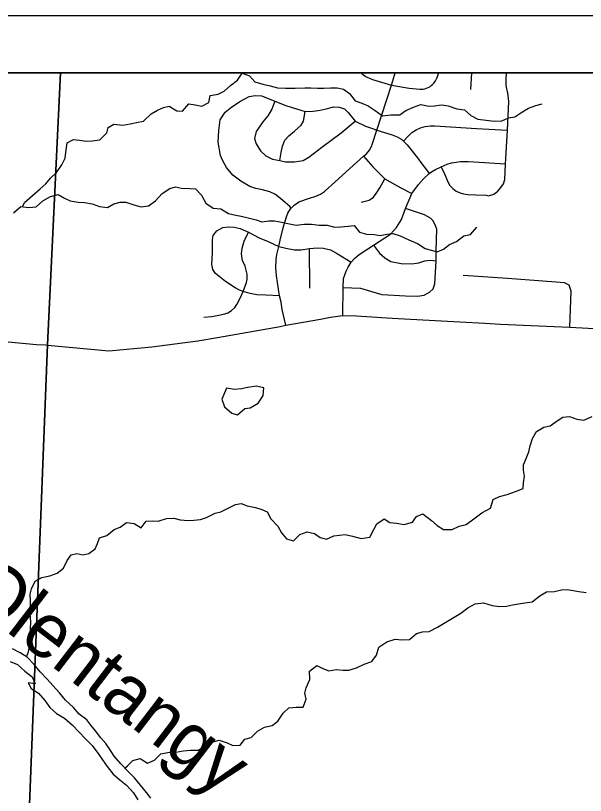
# Model space of a CAD drawing. Extents: x 0 to 34, y 0 to 22.
# Drawn here: x 17.909 to 18.903, y 8.924 to 10.284 of the extents above; entities that cross this region are included whole.
import ezdxf

# ---------------------------------------------------------------- set-up
doc = ezdxf.new("R2010")
doc.units = 0
for name, color, linetype in [('GM_X_Corporation', 7, 'Continuous'), ('GM_X_Major_River', 7, 'Continuous'), ('GM_X_Major_River_Text', 7, 'Continuous'), ('GM_X_Minor_Lake', 7, 'Continuous'), ('GM_X_Minor_River', 7, 'Continuous'), ('GM_X_State_Route', 7, 'Continuous'), ('GM_X_Township_Road', 7, 'Continuous'), ('SH_Data', 7, 'Continuous')]:
    doc.layers.add(name, color=color, linetype=linetype)

msp = doc.modelspace()

# ---------------------------------------------------------------- linework, layer by layer
at = {"layer": 'GM_X_Corporation'}
for points in [[(15.3473, 8.5302), (16.0546, 8.4904), (16.2652, 8.4813), (16.5003, 8.4668), (16.6112, 8.4601), (16.8906, 8.4459), (17.9061, 8.3935), (17.9129, 8.3931), (18.0835, 8.3895), (18.0903, 8.3893), (19.1791, 8.3374), (19.2255, 8.335), (19.3372, 8.3286), (19.3853, 8.3266), (19.4457, 8.3236), (19.4724, 8.3227), (19.4766, 8.3225), (19.5203, 8.3202), (19.5346, 8.3197), (19.5646, 8.318), (19.5646, 10.1841), (12.7646, 10.1841)], [(15.3473, 8.5302), (16.0546, 8.4904), (16.2652, 8.4813), (16.5003, 8.4668), (16.6112, 8.4601), (16.8906, 8.4459), (17.9061, 8.3935), (17.9129, 8.3931), (17.9187, 8.5404), (17.9296, 8.8181), (17.9647, 9.7099), (17.9872, 10.1841), (13.2832, 10.1841)]]:
    msp.add_lwpolyline(points, dxfattribs=at)
msp.add_lwpolyline([(19.5646, 8.318), (19.5646, 10.1841), (17.9872, 10.1841), (17.9647, 9.7099), (17.9296, 8.8181), (17.9187, 8.5404), (17.9129, 8.3931), (18.0835, 8.3895), (18.0903, 8.3893), (19.1791, 8.3374), (19.2255, 8.335), (19.3372, 8.3286), (19.3853, 8.3266), (19.4457, 8.3236), (19.4724, 8.3227), (19.4766, 8.3225), (19.5203, 8.3202), (19.5346, 8.3197)], close=True, dxfattribs=at)
at = {"layer": 'GM_X_Major_River'}
for points in [[(18.0663, 9.0144), (18.058, 9.0239), (18.0486, 9.0361), (18.0404, 9.0461), (18.0332, 9.0556), (18.02, 9.0652), (18.0099, 9.077), (17.9963, 9.09), (17.9854, 9.1026), (17.9738, 9.1152), (17.964, 9.1263), (17.952, 9.1389), (17.9415, 9.1522), (17.929, 9.1648), (17.917, 9.1721), (17.9038, 9.1794)], [(17.8995, 9.1571), (17.9127, 9.152), (17.9255, 9.1406), (17.9379, 9.1302), (17.9435, 9.1181), (17.931, 9.12), (17.9363, 9.1098), (17.9491, 9.1017), (17.96, 9.0891), (17.9686, 9.0769), (17.9807, 9.0666), (17.9943, 9.0585), (18.0082, 9.0459), (18.0195, 9.0344), (18.0308, 9.0222), (18.0428, 9.0104), (18.0541, 8.9951), (18.0604, 8.9856), (18.0687, 8.9738), (18.0792, 8.9608), (18.0909, 8.9505), (18.1026, 8.9413), (18.115, 8.9283), (18.1221, 8.9157)], [(18.1452, 8.919), (18.1373, 8.9285), (18.1268, 8.9415), (18.1163, 8.9541), (18.105, 8.9656), (18.0929, 8.9785), (18.0809, 8.9923), (18.0727, 9.0049), (18.0663, 9.0144)]]:
    msp.add_lwpolyline(points, dxfattribs=at)
at = {"layer": 'GM_X_Minor_Lake'}
for points in [[(18.2769, 9.634), (18.2689, 9.6147), (18.2735, 9.6018), (18.286, 9.5904), (18.2962, 9.5877), (18.3087, 9.5984), (18.3185, 9.5999), (18.3321, 9.6082), (18.3366, 9.615)], [(18.3366, 9.615), (18.3408, 9.6215), (18.342, 9.6344), (18.3287, 9.6378), (18.3143, 9.6352), (18.303, 9.6329), (18.2909, 9.6318), (18.2769, 9.634)]]:
    msp.add_lwpolyline(points, dxfattribs=at)
at = {"layer": 'GM_X_Minor_River'}
for points in [[(17.9209, 9.9507), (17.9244, 9.9578), (17.9383, 9.9704), (17.952, 9.9821), (17.9618, 9.9905), (17.9701, 10.0007), (17.9803, 10.0106), (17.9898, 10.0235), (17.9955, 10.0356), (17.9974, 10.05), (17.9989, 10.0622), (18.0102, 10.0682), (18.0204, 10.0667), (18.0329, 10.0648), (18.0428, 10.0659), (18.056, 10.0675), (18.0681, 10.0796), (18.0704, 10.0891), (18.0806, 10.0944), (18.0961, 10.0932), (18.109, 10.0951), (18.12, 10.0974), (18.1324, 10.1001), (18.1453, 10.1126), (18.1567, 10.119), (18.1672, 10.1239), (18.1771, 10.1262), (18.1903, 10.1182), (18.2002, 10.1175), (18.2115, 10.13), (18.2221, 10.1285), (18.2342, 10.1262), (18.246, 10.1327), (18.2482, 10.1448), (18.2626, 10.1471), (18.2728, 10.152), (18.2838, 10.1619), (18.2959, 10.1713), (18.3042, 10.1835), (18.3171, 10.1793), (18.3262, 10.1683), (18.3402, 10.1645), (18.3531, 10.1614), (18.3659, 10.158), (18.3799, 10.1573), (18.3966, 10.1573), (18.4136, 10.158), (18.4242, 10.158), (18.4356, 10.1576), (18.4465, 10.1576), (18.4583, 10.158), (18.47, 10.158), (18.481, 10.1557), (18.4912, 10.1481), (18.5014, 10.1356), (18.5132, 10.1314), (18.5238, 10.1269), (18.5363, 10.1185), (18.5491, 10.109), (18.5635, 10.1109), (18.579, 10.1109), (18.5896, 10.1185), (18.6029, 10.1246), (18.6161, 10.1291), (18.6297, 10.1261), (18.6399, 10.1268), (18.6521, 10.1287), (18.6634, 10.1268), (18.6789, 10.1215), (18.6922, 10.1196), (18.7032, 10.1097), (18.7153, 10.1037), (18.73, 10.1018), (18.744, 10.1002), (18.7569, 10.1006), (18.7686, 10.1059), (18.78, 10.1074), (18.7902, 10.1146), (18.8038, 10.1226), (18.8163, 10.1271), (18.8277, 10.1302)], [(17.9054, 9.94), (17.9183, 9.951), (17.9323, 9.9491), (17.9448, 9.9506), (17.9569, 9.9612), (17.9698, 9.9684), (17.9834, 9.9719), (17.9944, 9.9658), (18.0042, 9.9608), (18.0182, 9.9586), (18.0292, 9.9582), (18.0428, 9.9555), (18.0557, 9.9513), (18.0693, 9.9494), (18.0807, 9.9555), (18.0913, 9.9585), (18.1011, 9.9585), (18.1155, 9.954), (18.128, 9.9506), (18.1408, 9.9521), (18.1529, 9.9608), (18.1647, 9.9737), (18.1783, 9.9824), (18.1881, 9.9854), (18.1983, 9.9828), (18.2127, 9.9824), (18.2229, 9.9816), (18.2332, 9.9706), (18.2407, 9.957), (18.2536, 9.9482), (18.2669, 9.9467), (18.2805, 9.9391), (18.293, 9.9357), (18.3028, 9.9342), (18.3149, 9.9315), (18.3286, 9.9277), (18.3384, 9.9243), (18.3509, 9.9262), (18.3607, 9.9258), (18.3732, 9.9239), (18.3838, 9.9216), (18.3982, 9.9186), (18.4122, 9.9201), (18.4251, 9.9201), (18.4387, 9.9182), (18.4527, 9.9186), (18.4656, 9.9152), (18.4762, 9.9155), (18.4894, 9.9167), (18.4993, 9.9178), (18.5087, 9.906), (18.5212, 9.9026), (18.5345, 9.9022), (18.5451, 9.9007), (18.5564, 9.9026), (18.567, 9.9037), (18.5799, 9.8996), (18.595, 9.8927), (18.6102, 9.8863), (18.6234, 9.8779), (18.634, 9.8749), (18.6442, 9.8722), (18.6556, 9.8768), (18.6658, 9.8847), (18.6779, 9.89), (18.6908, 9.8999), (18.7025, 9.9022), (18.7135, 9.9147)], [(17.9281, 9.1654), (17.9319, 9.1743), (17.9338, 9.1872), (17.9346, 9.1986), (17.9349, 9.2134), (17.9357, 9.2263), (17.9345, 9.2395), (17.9349, 9.2521), (17.9349, 9.2623), (17.9345, 9.2744), (17.9368, 9.2839), (17.9432, 9.2976), (17.955, 9.304), (17.969, 9.3067), (17.9814, 9.3112), (17.9928, 9.3203), (17.9992, 9.3332), (18.006, 9.3435), (18.0159, 9.3454), (18.0261, 9.3431), (18.0371, 9.3454), (18.0477, 9.3537), (18.0518, 9.3632), (18.0552, 9.3727), (18.0685, 9.3769), (18.0809, 9.3875), (18.0912, 9.3913), (18.1025, 9.3996), (18.1158, 9.3981), (18.1282, 9.3905), (18.1369, 9.4019), (18.1472, 9.4026), (18.1578, 9.4019), (18.1721, 9.4064), (18.185, 9.4072), (18.196, 9.4045), (18.21, 9.403), (18.2202, 9.4037), (18.2316, 9.4049), (18.2422, 9.4087), (18.2573, 9.4162), (18.2671, 9.4185), (18.2796, 9.4246), (18.2929, 9.431), (18.3027, 9.4329), (18.3129, 9.4287), (18.3273, 9.4257), (18.3383, 9.4223), (18.3481, 9.4181), (18.3542, 9.406), (18.3663, 9.3934), (18.3731, 9.3817), (18.3815, 9.3714), (18.3936, 9.3676), (18.4049, 9.3786), (18.4174, 9.3832), (18.4303, 9.3805), (18.4405, 9.3737), (18.4511, 9.3706), (18.464, 9.3763), (18.4738, 9.3775), (18.484, 9.3786), (18.4965, 9.3756), (18.512, 9.3718), (18.5268, 9.3744), (18.5336, 9.3877), (18.5389, 9.3976), (18.5517, 9.4059), (18.5616, 9.3998), (18.5733, 9.3983), (18.5869, 9.396), (18.6013, 9.4002), (18.6085, 9.4104), (18.6195, 9.4146), (18.6346, 9.4032), (18.6445, 9.3945), (18.6555, 9.3873), (18.6706, 9.3876), (18.6827, 9.3933), (18.6948, 9.396), (18.7081, 9.4062), (18.7224, 9.4165), (18.7372, 9.4248), (18.7421, 9.44), (18.7531, 9.4449), (18.7663, 9.4483), (18.7811, 9.454), (18.7943, 9.4593), (18.7947, 9.4692), (18.7966, 9.4806), (18.7947, 9.4908), (18.7947, 9.5003), (18.7996, 9.5113), (18.8041, 9.5231), (18.8068, 9.5337), (18.8109, 9.5462), (18.8174, 9.5587), (18.8306, 9.5659), (18.8412, 9.5686), (18.8537, 9.5773), (18.8635, 9.5834)], [(18.8635, 9.5834), (18.8749, 9.5845), (18.8881, 9.58), (18.8999, 9.5784), (18.9146, 9.5849)], [(18.0997, 8.9712), (18.1042, 8.975), (18.1133, 8.9845), (18.1266, 8.9879), (18.1394, 8.9799), (18.1512, 8.9852), (18.1625, 8.9962), (18.1773, 8.9989), (18.1886, 8.9992), (18.2015, 9.0011), (18.2144, 9.0027), (18.228, 9.0023), (18.2408, 9.0114), (18.2511, 9.0167), (18.2643, 9.0197), (18.2779, 9.0152), (18.2878, 9.0106), (18.301, 9.0114), (18.309, 9.0216), (18.3199, 9.0246), (18.3309, 9.0356), (18.343, 9.0428), (18.3563, 9.0455), (18.3665, 9.0531), (18.3755, 9.0671), (18.3854, 9.0762), (18.3982, 9.0777), (18.4107, 9.0777), (18.416, 9.0914), (18.4138, 9.102), (18.4156, 9.1115), (18.4221, 9.1255), (18.4217, 9.1403), (18.4345, 9.1502), (18.4451, 9.1449), (18.4554, 9.1411), (18.4682, 9.143), (18.4803, 9.1422), (18.4902, 9.1422), (18.5038, 9.146), (18.5171, 9.1524), (18.5303, 9.157), (18.5386, 9.168), (18.5424, 9.1824), (18.5564, 9.1915), (18.5712, 9.1961), (18.5825, 9.1949), (18.5961, 9.1953), (18.6082, 9.2059), (18.6185, 9.2089), (18.6306, 9.2097), (18.6449, 9.2173), (18.6593, 9.226), (18.6741, 9.2343), (18.6854, 9.2415), (18.6979, 9.251), (18.7108, 9.2579), (18.7252, 9.2597), (18.7403, 9.2548), (18.7532, 9.2529), (18.7653, 9.254), (18.7759, 9.2563), (18.7861, 9.2578), (18.7971, 9.2593), (18.8103, 9.2612), (18.8236, 9.2719), (18.8353, 9.2787), (18.8489, 9.2794), (18.861, 9.2821), (18.8709, 9.2828), (18.8818, 9.2813), (18.8917, 9.2794), (18.9042, 9.2775)]]:
    msp.add_lwpolyline(points, dxfattribs=at)
at = {"layer": 'GM_X_State_Route'}
for points in [[(17.6666, 9.7372), (17.7408, 9.7296), (17.9454, 9.7105), (17.9612, 9.7097), (17.9649, 9.7093), (18.0719, 9.6992), (18.1468, 9.7063), (18.2271, 9.7165), (18.2615, 9.7226), (18.3705, 9.7416), (18.3806, 9.744), (18.4407, 9.7546), (18.4581, 9.7577), (18.4796, 9.7606), (18.5035, 9.7601), (18.5661, 9.7565), (18.684, 9.7499), (18.7272, 9.7474)], [(18.7272, 9.7474), (18.7546, 9.7458), (18.8482, 9.7416), (18.8759, 9.7408)], [(18.8759, 9.7408), (18.9398, 9.737), (18.9492, 9.7362), (19.0653, 9.7309), (19.0969, 9.7281), (19.1088, 9.7275)]]:
    msp.add_lwpolyline(points, dxfattribs=at)
at = {"layer": 'GM_X_Township_Road'}
for p, q in [((18.7032, 10.155), (18.705, 10.1841)), ((18.422, 9.8088), (18.4217, 9.8778))]:
    msp.add_line(p, q, dxfattribs=at)
for points in [[(18.3806, 9.744), (18.3741, 9.7716), (18.3721, 9.7844), (18.3696, 9.7954), (18.3641, 9.8298), (18.3632, 9.8441), (18.3638, 9.8585), (18.365, 9.8675), (18.368, 9.8812), (18.3705, 9.8923), (18.3766, 9.9163), (18.3813, 9.9329), (18.3837, 9.9394), (18.3886, 9.9468), (18.39, 9.9482), (18.3947, 9.9532), (18.4006, 9.9577), (18.4029, 9.9592), (18.4216, 9.9657), (18.4328, 9.9692), (18.4406, 9.9727), (18.4477, 9.9775), (18.4489, 9.9785), (18.4658, 9.9933), (18.4854, 10.0113), (18.516, 10.0386), (18.5209, 10.043), (18.5262, 10.0496), (18.5302, 10.057), (18.5312, 10.0594), (18.5391, 10.0842), (18.5645, 10.1629), (18.57, 10.1799), (18.5713, 10.1841)], [(18.5122, 10.1841), (18.5131, 10.1829), (18.5156, 10.1805), (18.518, 10.1788), (18.5183, 10.1783), (18.5318, 10.1726), (18.5645, 10.1629)], [(18.5645, 10.1629), (18.5956, 10.1577), (18.614, 10.1555), (18.6171, 10.1555), (18.6201, 10.1558), (18.6231, 10.1565), (18.626, 10.1574), (18.6288, 10.1586), (18.6315, 10.1601), (18.634, 10.1619), (18.6363, 10.1639), (18.6384, 10.1661), (18.6415, 10.1702), (18.6446, 10.1763), (18.6457, 10.1795), (18.6465, 10.1829), (18.6467, 10.1841)], [(18.764, 10.0349), (18.7668, 10.0844), (18.7695, 10.1342), (18.7674, 10.1491), (18.7668, 10.151), (18.765, 10.1593), (18.7645, 10.1636), (18.7645, 10.1721), (18.765, 10.1841)], [(18.39, 9.9482), (18.3871, 9.9512), (18.3795, 9.9579), (18.3718, 9.9642), (18.3651, 9.9699), (18.3612, 9.9723), (18.3526, 9.9765), (18.3396, 9.9803), (18.3279, 9.9822), (18.3177, 9.9857), (18.3017, 9.9951), (18.2881, 10.0056), (18.2767, 10.0189), (18.2697, 10.0318), (18.2664, 10.04), (18.2625, 10.0632), (18.2633, 10.0834), (18.266, 10.102), (18.2745, 10.1155), (18.2865, 10.1252), (18.3016, 10.1349), (18.3167, 10.1427), (18.3272, 10.1446), (18.338, 10.1442), (18.3516, 10.1388), (18.3613, 10.1349), (18.3802, 10.1275), (18.3988, 10.1213), (18.4143, 10.1167), (18.4279, 10.1175), (18.4402, 10.119), (18.4507, 10.1217), (18.4639, 10.1248), (18.4735, 10.1244), (18.4828, 10.1217), (18.489, 10.1151), (18.5014, 10.1), (18.5193, 10.0911), (18.5315, 10.087), (18.5391, 10.0842), (18.5657, 10.0759), (18.5744, 10.0727), (18.5825, 10.0677), (18.5858, 10.0649), (18.5922, 10.0589), (18.6098, 10.0362), (18.6177, 10.0255), (18.6257, 10.015), (18.6302, 10.0084)], [(18.3613, 10.1349), (18.3558, 10.1206), (18.3493, 10.1093), (18.3404, 10.0985), (18.3326, 10.0876), (18.3284, 10.0818), (18.326, 10.0698), (18.3284, 10.0601), (18.3361, 10.0481), (18.3458, 10.0392), (18.3574, 10.0338), (18.3702, 10.0315), (18.3798, 10.0288), (18.3953, 10.0288), (18.4108, 10.0311), (18.4205, 10.0373), (18.443, 10.0547), (18.4767, 10.0798), (18.5014, 10.1)], [(18.3702, 10.0315), (18.3725, 10.0454), (18.3744, 10.0563), (18.3787, 10.0667), (18.3857, 10.0741), (18.3953, 10.0822), (18.407, 10.0931), (18.4112, 10.1), (18.4143, 10.1167)], [(18.5858, 10.0649), (18.5939, 10.0739), (18.6004, 10.0802), (18.6076, 10.085), (18.6154, 10.0884), (18.6234, 10.0904), (18.6327, 10.0917), (18.6405, 10.0916), (18.6676, 10.0902), (18.7128, 10.0874), (18.7668, 10.0844)], [(18.4796, 9.7606), (18.4806, 9.8096), (18.4808, 9.8256), (18.4857, 9.8385), (18.4889, 9.8452), (18.4941, 9.854), (18.5004, 9.8606), (18.5085, 9.8673), (18.5218, 9.8758), (18.5333, 9.8834), (18.5631, 9.9026), (18.5732, 9.9145), (18.582, 9.9285), (18.5893, 9.9478), (18.6002, 9.9737), (18.6119, 9.9897), (18.6205, 9.9996), (18.6302, 10.0084), (18.6346, 10.0115), (18.6414, 10.0157), (18.6511, 10.0205), (18.6618, 10.0249), (18.6694, 10.027), (18.6733, 10.0279), (18.6851, 10.0295), (18.6991, 10.0296), (18.7635, 10.0254)], [(18.516, 10.0386), (18.5322, 10.0205), (18.5533, 9.9994), (18.581, 9.9838), (18.6002, 9.9737)], [(18.6511, 10.0205), (18.6571, 10.008), (18.6633, 9.9929), (18.6664, 9.9879), (18.6715, 9.9823), (18.6776, 9.9777), (18.6843, 9.9746), (18.6903, 9.9733), (18.6978, 9.9722), (18.7117, 9.9714), (18.7297, 9.9707), (18.7336, 9.9699), (18.743, 9.9725), (18.75, 9.9779), (18.7554, 9.9843), (18.7598, 9.9903), (18.7621, 9.9984), (18.7635, 10.0254), (18.764, 10.0349)], [(18.512, 9.9588), (18.5256, 9.9623), (18.5334, 9.9674), (18.5377, 9.9736), (18.5444, 9.9838), (18.5533, 9.9994)], [(18.4806, 9.8096), (18.5107, 9.8084), (18.5282, 9.8035), (18.5481, 9.7975), (18.589, 9.7951), (18.6101, 9.7945), (18.6215, 9.7963), (18.6312, 9.8017), (18.6372, 9.8072), (18.64, 9.8161), (18.6425, 9.8561), (18.6428, 9.8736), (18.6438, 9.9114), (18.6408, 9.9193), (18.6366, 9.9265), (18.633, 9.9307), (18.6221, 9.9367), (18.5893, 9.9478)], [(18.3696, 9.7954), (18.3457, 9.7961), (18.3296, 9.7971), (18.3183, 9.799), (18.3062, 9.8028), (18.2995, 9.805), (18.292, 9.8089), (18.2749, 9.82), (18.258, 9.8339), (18.2532, 9.8414), (18.2515, 9.8501), (18.2524, 9.8702), (18.2528, 9.8935), (18.2535, 9.9005), (18.2602, 9.9087), (18.2708, 9.9143), (18.2804, 9.9157), (18.2903, 9.9147), (18.3005, 9.9126), (18.3154, 9.9062), (18.3338, 9.8966), (18.3497, 9.8899), (18.368, 9.8812)], [(18.3062, 9.8028), (18.312, 9.8185), (18.3129, 9.8243), (18.3129, 9.8328), (18.3094, 9.8468), (18.3051, 9.857), (18.303, 9.8683), (18.3041, 9.8786), (18.3076, 9.8903), (18.3154, 9.9062)], [(18.368, 9.8812), (18.3806, 9.8783), (18.3954, 9.8753), (18.4073, 9.8757), (18.4217, 9.8778), (18.4357, 9.8792), (18.4462, 9.8781), (18.4581, 9.8757), (18.4689, 9.8697), (18.4791, 9.8631), (18.4941, 9.854)], [(18.5333, 9.8834), (18.5438, 9.8694), (18.5533, 9.8613), (18.5638, 9.855), (18.5816, 9.8515), (18.6002, 9.8512), (18.6121, 9.8526), (18.6229, 9.8561), (18.6324, 9.8575), (18.6425, 9.8561)], [(18.8759, 9.7408), (18.8782, 9.8035), (18.8745, 9.8138), (18.8667, 9.818), (18.8517, 9.8192), (18.7673, 9.8252), (18.6896, 9.8307)], [(18.2372, 9.7581), (18.2509, 9.7593), (18.2608, 9.7608), (18.2739, 9.7635), (18.2794, 9.7658), (18.2859, 9.7698), (18.2914, 9.7751), (18.2949, 9.7799), (18.3009, 9.7909), (18.3062, 9.8028)]]:
    msp.add_lwpolyline(points, dxfattribs=at)
at = {"layer": 'SH_Data'}
for p, q in [((12.6646, 10.2841), (19.6646, 10.2841)), ((12.7646, 10.1841), (19.5646, 10.1841))]:
    msp.add_line(p, q, dxfattribs=at)

# ---------------------------------------------------------------- texts
at = {"layer": 'GM_X_Major_River_Text'}
msp.add_text('Olentangy', height=0.09469, rotation=322.5421, dxfattribs=at).set_placement((17.8123, 9.2708))

doc.saveas('drawing.dxf')
